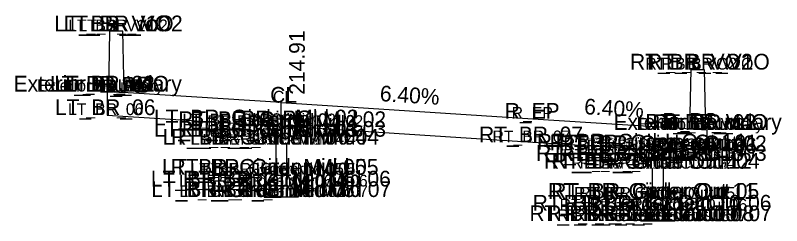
# Model space of a CAD drawing. Extents: x 1977765 to 1980293, y 795569 to 815181.
# Drawn here: x 1978023.5 to 1978072.25, y 809625.7 to 809639.08 of the extents above; entities that cross this region are included whole.
import ezdxf

# ---------------------------------------------------------------- set-up
doc = ezdxf.new("R2010")
doc.units = 0
for name, color, linetype in [('RD_Sketch5', 7, 'Continuous'), ('RD_XS_NewRW', 7, 'Continuous'), ('RD_XS_PaveOvlay', 7, 'Continuous'), ('RD_XS_TX_Elev_PR', 7, 'Continuous'), ('RD_XS_TX_Slope', 7, 'Continuous')]:
    doc.layers.add(name, color=color, linetype=linetype)

msp = doc.modelspace()

# ---------------------------------------------------------------- linework, layer by layer
at = {"layer": 'RD_XS_PaveOvlay'}
for points in [[(1978030.416, 809634.166), (1978030.332, 809638.063), (1978029.499, 809638.063), (1978029.416, 809634.23)], [(1978030.416, 809634.166), (1978030.332, 809638.063), (1978029.499, 809638.063), (1978029.416, 809634.23)], [(1978066.416, 809631.862), (1978066.499, 809635.631), (1978067.332, 809635.631), (1978067.416, 809631.798)], [(1978066.416, 809631.862), (1978066.499, 809635.631), (1978067.332, 809635.631), (1978067.416, 809631.798)], [(1978040.416, 809633.526), (1978029.332, 809634.235)], [(1978029.332, 809634.235), (1978029.332, 809632.735)], [(1978040.416, 809633.526), (1978029.332, 809634.235)], [(1978029.332, 809634.235), (1978029.332, 809632.735)], [(1978029.416, 809634.23), (1978030.416, 809634.166)], [(1978029.416, 809634.23), (1978030.416, 809634.166)], [(1978040.416, 809632.026), (1978040.416, 809633.526)], [(1978040.416, 809633.526), (1978056.416, 809632.502), (1978067.499, 809631.793)], [(1978040.416, 809632.026), (1978040.416, 809633.526)], [(1978040.416, 809632.026), (1978040.416, 809633.526)], [(1978040.416, 809633.526), (1978056.416, 809632.502), (1978067.499, 809631.793)], [(1978040.416, 809632.026), (1978040.416, 809633.526)], [(1978029.332, 809632.735), (1978040.416, 809632.026)], [(1978029.332, 809632.735), (1978040.416, 809632.026)], [(1978040.416, 809632.026), (1978039.582, 809632.079)], [(1978039.582, 809632.079), (1978039.582, 809631.359)], [(1978040.416, 809632.026), (1978039.582, 809632.079)], [(1978039.582, 809632.079), (1978039.582, 809631.359)], [(1978040.416, 809632.026), (1978041.249, 809631.973)], [(1978067.499, 809630.293), (1978056.416, 809631.002), (1978040.416, 809632.026)], [(1978040.416, 809632.026), (1978041.249, 809631.973)], [(1978067.499, 809630.293), (1978056.416, 809631.002), (1978040.416, 809632.026)], [(1978041.249, 809631.973), (1978041.249, 809631.359)], [(1978041.249, 809631.973), (1978041.249, 809631.359)], [(1978067.416, 809631.798), (1978066.416, 809631.862)], [(1978067.416, 809631.798), (1978066.416, 809631.862)], [(1978067.499, 809631.793), (1978067.499, 809630.293)], [(1978067.499, 809631.793), (1978067.499, 809630.293)], [(1978039.582, 809631.359), (1978040.082, 809630.859)], [(1978039.582, 809631.359), (1978040.082, 809630.859)], [(1978041.249, 809631.359), (1978040.749, 809630.859)], [(1978041.249, 809631.359), (1978040.749, 809630.859)], [(1978040.082, 809630.859), (1978040.082, 809628.943)], [(1978040.082, 809630.859), (1978040.082, 809628.943)], [(1978040.749, 809630.859), (1978040.749, 809628.943)], [(1978040.749, 809630.859), (1978040.749, 809628.943)], [(1978063.541, 809630.546), (1978064.374, 809630.493), (1978065.207, 809630.439)], [(1978063.541, 809629.826), (1978063.541, 809630.546)], [(1978063.541, 809630.546), (1978064.374, 809630.493), (1978065.207, 809630.439)], [(1978063.541, 809629.826), (1978063.541, 809630.546)], [(1978065.207, 809630.439), (1978065.207, 809629.826)], [(1978065.207, 809630.439), (1978065.207, 809629.826)], [(1978064.041, 809629.326), (1978063.541, 809629.826)], [(1978064.041, 809629.326), (1978063.541, 809629.826)], [(1978065.207, 809629.826), (1978064.707, 809629.326)], [(1978065.207, 809629.826), (1978064.707, 809629.326)], [(1978064.041, 809627.409), (1978064.041, 809629.326)], [(1978064.041, 809627.409), (1978064.041, 809629.326)], [(1978064.707, 809629.326), (1978064.707, 809627.409)], [(1978064.707, 809629.326), (1978064.707, 809627.409)], [(1978040.082, 809628.943), (1978039.332, 809628.193)], [(1978040.082, 809628.943), (1978039.332, 809628.193)], [(1978040.749, 809628.943), (1978041.499, 809628.193)], [(1978040.749, 809628.943), (1978041.499, 809628.193)], [(1978039.332, 809628.193), (1978039.332, 809627.526)], [(1978039.332, 809628.193), (1978039.332, 809627.526)], [(1978041.499, 809628.193), (1978041.499, 809627.526)], [(1978041.499, 809628.193), (1978041.499, 809627.526)], [(1978039.332, 809627.526), (1978040.416, 809627.526)], [(1978039.332, 809627.526), (1978040.416, 809627.526)], [(1978041.499, 809627.526), (1978040.416, 809627.526)], [(1978041.499, 809627.526), (1978040.416, 809627.526)], [(1978063.291, 809626.659), (1978064.041, 809627.409)], [(1978063.291, 809626.659), (1978064.041, 809627.409)], [(1978064.707, 809627.409), (1978065.457, 809626.659)], [(1978064.707, 809627.409), (1978065.457, 809626.659)], [(1978063.291, 809625.993), (1978063.291, 809626.659)], [(1978063.291, 809625.993), (1978063.291, 809626.659)], [(1978065.457, 809626.659), (1978065.457, 809625.993)], [(1978065.457, 809626.659), (1978065.457, 809625.993)], [(1978065.457, 809625.993), (1978064.374, 809625.993), (1978063.291, 809625.993)], [(1978065.457, 809625.993), (1978064.374, 809625.993), (1978063.291, 809625.993)]]:
    msp.add_lwpolyline(points, dxfattribs=at)

# ---------------------------------------------------------------- texts
at = {"layer": 'RD_Sketch5'}
for s, p in [('LT_BR_V1O', (1978025.983, 809638.063)), ('LT_BR_VO2', (1978026.565, 809638.063)), ('RT_BR_VO2', (1978062.605, 809635.631)), ('RT_BR_V1O', (1978063.691, 809635.631)), ('Exterior Boundary', (1978023.387, 809634.235)), ('LT_BR_V4O', (1978025.695, 809634.23)), ('LT_BR_02', (1978025.974, 809634.235)), ('L_PS', (1978028.798, 809634.166)), ('CL', (1978039.711, 809633.526)), ('LT_BR_06', (1978026.021, 809632.735)), ('R_EP', (1978054.632, 809632.502)), ('LT_BR_Girder Mid 02', (1978032.319, 809632.079)), ('RT_BR_Girder Mid 02', (1978033.859, 809631.973)), ('BR_PGL', (1978037.876, 809632.026)), ('LT_BR_Girder Mid 03', (1978032.311, 809631.359)), ('RT_BR_Girder Mid 03', (1978033.851, 809631.359)), ('Exterior Boundary', (1978061.554, 809631.793)), ('RT_BR_V4O', (1978063.569, 809631.798)), ('RT_BR_02', (1978064.015, 809631.793)), ('R_PS', (1978064.672, 809631.862)), ('RT_BR_07', (1978053.002, 809631.002)), ('LT_BR_Girder Mid 04', (1978032.866, 809630.859)), ('RT_BR_Girder Mid 04', (1978033.407, 809630.859)), ('RT_BR_Girder Out 14', (1978056.678, 809630.546)), ('RT_BR_Girder Out 01', (1978057.496, 809630.493)), ('RT_BR_Girder Out 02', (1978058.077, 809630.439)), ('RT_BR_06', (1978064.062, 809630.293)), ('RT_BR_Girder Out 13', (1978056.623, 809629.826)), ('RT_BR_Girder Out 03', (1978058.07, 809629.826)), ('LT_BR_Girder Mid 05', (1978032.834, 809628.943)), ('RT_BR_Girder Mid 05', (1978033.375, 809628.943)), ('RT_BR_Girder Out 12', (1978057.131, 809629.326)), ('RT_BR_Girder Out 04', (1978057.625, 809629.326)), ('LT_BR_Girder Mid 06', (1978032.116, 809628.193)), ('RT_BR_Girder Mid 06', (1978034.157, 809628.193)), ('LT_BR_Girder Mid 07', (1978032.139, 809627.526)), ('RT_BR_Girder Mid 07', (1978034.18, 809627.526)), ('BR_Girder Mid 08', (1978034.392, 809627.526)), ('RT_BR_Girder Out 11', (1978057.383, 809627.409)), ('RT_BR_Girder Out 05', (1978057.593, 809627.409)), ('RT_BR_Girder Out 10', (1978056.413, 809626.659)), ('RT_BR_Girder Out 06', (1978058.375, 809626.659)), ('RT_BR_Girder Out 09', (1978056.208, 809625.993)), ('RT_BR_Girder Out 08', (1978057.28, 809625.993)), ('RT_BR_Girder Out 07', (1978058.398, 809625.993))]:
    msp.add_text(s, height=1, dxfattribs=at).set_placement(p)
at = {"layer": 'RD_XS_NewRW'}
for s, p in [('LT_BR_V1O', (1978026.862, 809638.063)), ('LT_BR_VO2', (1978027.507, 809638.063)), ('RT_BR_VO2', (1978063.579, 809635.631)), ('RT_BR_V1O', (1978064.601, 809635.631)), ('Exterior Boundary', (1978024.874, 809634.235)), ('LT_BR_V4O', (1978026.625, 809634.23)), ('LT_BR_02', (1978026.814, 809634.235)), ('L_PS', (1978029.202, 809634.166)), ('CL', (1978039.887, 809633.526)), ('LT_BR_06', (1978026.849, 809632.735)), ('R_EP', (1978055.078, 809632.502)), ('LT_BR_Girder Mid 02', (1978034.135, 809632.079)), ('RT_BR_Girder Mid 02', (1978035.707, 809631.973)), ('BR_PGL', (1978038.511, 809632.026)), ('Exterior Boundary', (1978063.04, 809631.793)), ('RT_BR_V4O', (1978064.531, 809631.798)), ('RT_BR_02', (1978064.886, 809631.793)), ('R_PS', (1978065.108, 809631.862)), ('LT_BR_Girder Mid 03', (1978034.129, 809631.359)), ('RT_BR_Girder Mid 03', (1978035.701, 809631.359)), ('LT_BR_Girder Mid 04', (1978034.67, 809630.859)), ('RT_BR_Girder Mid 04', (1978035.242, 809630.859)), ('RT_BR_07', (1978053.856, 809631.002)), ('RT_BR_Girder Out 14', (1978058.394, 809630.546)), ('RT_BR_Girder Out 01', (1978059.216, 809630.493)), ('RT_BR_Girder Out 02', (1978059.86, 809630.439)), ('RT_BR_06', (1978064.921, 809630.293)), ('RT_BR_Girder Out 13', (1978058.353, 809629.826)), ('RT_BR_Girder Out 03', (1978059.854, 809629.826)), ('RT_BR_Girder Out 12', (1978058.859, 809629.326)), ('RT_BR_Girder Out 04', (1978059.395, 809629.326)), ('LT_BR_Girder Mid 05', (1978034.646, 809628.943)), ('RT_BR_Girder Mid 05', (1978035.219, 809628.943)), ('LT_BR_Girder Mid 06', (1978033.92, 809628.193)), ('RT_BR_Girder Mid 06', (1978035.992, 809628.193)), ('LT_BR_Girder Mid 07', (1978033.938, 809627.526)), ('BR_Girder Mid 08', (1978035.898, 809627.526)), ('RT_BR_Girder Mid 07', (1978036.01, 809627.526)), ('RT_BR_Girder Out 11', (1978059.048, 809627.409)), ('RT_BR_Girder Out 05', (1978059.372, 809627.409)), ('RT_BR_Girder Out 10', (1978058.132, 809626.659)), ('RT_BR_Girder Out 06', (1978060.145, 809626.659)), ('RT_BR_Girder Out 09', (1978057.979, 809625.993)), ('RT_BR_Girder Out 08', (1978059.053, 809625.993)), ('RT_BR_Girder Out 07', (1978060.163, 809625.993))]:
    msp.add_text(s, height=0.75, dxfattribs=at).set_placement(p)
at = {"layer": 'RD_XS_TX_Elev_PR'}
msp.add_text('214.91', height=1, rotation=90, dxfattribs=at).set_placement((1978041.916, 809634.026))
at = {"layer": 'RD_XS_TX_Slope'}
for p in [(1978046.668, 809633.627), (1978059.668, 809632.795)]:
    msp.add_text('6.40%', height=1, rotation=356.3381, dxfattribs=at).set_placement(p)

doc.saveas('drawing.dxf')
